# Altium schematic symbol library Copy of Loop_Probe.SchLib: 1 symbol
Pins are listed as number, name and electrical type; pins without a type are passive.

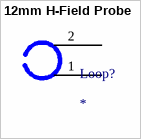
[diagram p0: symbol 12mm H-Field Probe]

## 12mm H-Field Probe
designator Loop?
pins: 1, 2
